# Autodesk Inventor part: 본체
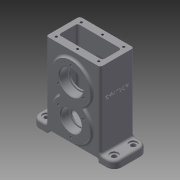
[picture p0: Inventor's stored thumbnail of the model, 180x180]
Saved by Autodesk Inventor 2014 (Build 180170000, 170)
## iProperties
Created: 2020-03
Part Number: 본체
Material: Aluminum 6061
Document SubType Name: Modeling
Designer: mduedu
Density: 2.71 g/cm^3
Appearance: Default
Mass: 597.031 g
Surface Area: 576.062 cm^2
Volume: 220.307 cm^3
Author: mduedu
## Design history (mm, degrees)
sketch "스케치1"
  geometry: L1 (-56, 0)-(56, 0); L2 (56, 0)-(56, 10); L3 (-56, 10)-(-56, 0); L4 (37, 10)-(37, 114); L5 (37, 114)-(-37, 114); L6 (-37, 114)-(-37, 10); L7 (56, 10)-(37, 10); L8 (-37, 10)-(-56, 10); L9 (0, 0)-(0, 114); 1 further point
  constraints: 18 end point, 5 parallel, 2 midpoint, 2 vertical, 1 coincident, 1 horizontal, 1 perpendicular
  dimensions: "d0" = 112 distance of L1.start L1.end; "d2" = 10 distance of L1.end L2.end; "d3" = 114 distance between parallel lines of L5 L1; "d4" = 74 distance between parallel lines of L4 L6
extrude "돌출1" new body sketch "스케치1" stored distance "d5" = 46; taper "d6" = 0 deg
sketch "스케치2"
  geometry: L1 (56, 0)-(-56, 0) reference; C1 r 26 at (0, 34); C2 r 26 at (0, 79); 1 further point
  constraints: 2 centre point, 2 vertical alignment, 1 equal radius
  dimensions: "d7" = 52 diameter of C2; "d9" = 34 distance from line of C1.centre L1; "d10" = 45 distance of C2.centre C1.centre
extrude "돌출2" join sketch "스케치2" stored distance "d11" = 52; taper "d12" = 0 deg
fillet "모깎기1" dims "d13" = 3
fillet "모깎기2" dims "d14" = 3
fillet "모깎기3" dims "d15" = 10
fillet "모깎기4" dims "d16" = 3
fillet "모깎기5" dims "d17" = 3
sketch "스케치3"
  geometry: L1 (-30, 114)-(30, 114); L2 (30, 114)-(30, 13); L3 (30, 13)-(-30, 13); L4 (-30, 13)-(-30, 114); L5 (-34, 114)-(34, 114) reference; L6 (46, 0)-(-46, 0) reference; 2 further points
  constraints: 8 end point, 2 parallel, 1 collinear, 1 horizontal, 1 midpoint, 1 perpendicular, 1 vertical alignment
  dimensions: "d18" = 60 distance between parallel lines of L2 L4; "d20" = 13 distance between parallel lines of L3 L6
extrude "돌출3" cut sketch "스케치3" stored distance "d21" = 26; taper "d22" = 0 deg
fillet "모깎기6" dims "d23" = 3
fillet "모깎기7" dims "d24" = 3
sketch "스케치4"
  geometry: L1 (-35, 0)-(35, 0); L2 (35, 0)-(35, 5); L3 (35, 5)-(-35, 5); L4 (-35, 5)-(-35, 0); 2 further points
  constraints: 8 end point, 2 parallel, 1 coincident, 1 horizontal, 1 midpoint, 1 perpendicular
  dimensions: "d25" = 70 distance of L1.start L1.end; "d27" = 5 distance of L1.end L2.end
extrude "돌출4" cut sketch "스케치4" stored distance "d28" = 26; taper "d29" = 0 deg
fillet "모깎기8" dims "d30" = 3
sketch "스케치5"
  geometry: A1 r 10 centre (-86, 33) between (-86, 43) and (-96, 33) reference; A2 r 10 centre (-86, 7) between (-96, 7) and (-86, -3) reference; A3 r 10 centre (6, 7) between (6, -3) and (16, 7) reference; A4 r 10 centre (6, 33) between (16, 33) and (6, 43) reference; 5 further points
  constraints: 4 coincident
hole "구멍1" sketch "스케치5" at (-86, 33), (-86, 7), (6, 7), (6, 33) diameter "d31" = 6.6; stored, may be unused: countersink angle "d35" = 90 deg, drill point angle "d37" = 118 deg; dims "d32" = 6, "d33" = 11, "d34" = 2, "d36" = 8
sketch "스케치6"
  geometry: A1 r 26 centre (0, 34) between (-16.403, 54.172) and (16.403, 54.172) reference; A2 r 3 centre (18.296, 56.5) between (16.403, 58.828) and (16.403, 54.172) reference; A3 r 26 centre (0, 79) between (16.403, 58.828) and (-16.403, 58.828) reference; A4 r 3 centre (-18.296, 56.5) between (-16.403, 54.172) and (-16.403, 58.828) reference; 2 further points
  constraints: 1 coincident
hole "구멍2" sketch "스케치6" at (0, 79) diameter "d38" = 28; stored, may be unused: countersink angle "d42" = 90 deg, drill point angle "d44" = 118 deg; dims "d39" = 6, "d40" = 32, "d41" = 11, "d43" = 8
sketch "스케치7"
  geometry: C1 r 16 at (0, 79) reference; A1 r 26 centre (0, 34) between (-16.403, 54.172) and (16.403, 54.172) reference; A2 r 3 centre (18.296, 56.5) between (16.403, 58.828) and (16.403, 54.172) reference; A3 r 26 centre (0, 79) between (16.403, 58.828) and (-16.403, 58.828) reference; A4 r 3 centre (-18.296, 56.5) between (-16.403, 54.172) and (-16.403, 58.828) reference; 2 further points
  constraints: 1 coincident
hole "구멍3" sketch "스케치7" at (0, 34) diameter "d45" = 24; stored, may be unused: countersink angle "d49" = 90 deg, drill point angle "d51" = 118 deg; dims "d46" = 6, "d47" = 28, "d48" = 11, "d50" = 8
sketch "스케치8"
  geometry: C1 r 14 at (0, 34) reference; A1 r 26 centre (0, 34) between (-16.403, 54.172) and (16.403, 54.172) reference; A2 r 3 centre (18.296, 56.5) between (16.403, 58.828) and (16.403, 54.172) reference; A3 r 26 centre (0, 79) between (16.403, 58.828) and (-16.403, 58.828) reference; A4 r 3 centre (-18.296, 56.5) between (-16.403, 54.172) and (-16.403, 58.828) reference; 2 further points
  constraints: 1 coincident
hole "구멍4" sketch "스케치8" at (0, 79) diameter "d52" = 24; stored, may be unused: countersink angle "d56" = 90 deg, drill point angle "d58" = 118 deg; dims "d53" = 6, "d54" = 28, "d55" = 11, "d57" = 8
sketch "스케치9" dims "d59" = 40
  geometry: C1 r 14 at (0, 34) reference; C2 r 16 at (0, 79) reference; A1 r 26 centre (0, 34) between (-16.403, 54.172) and (16.403, 54.172) reference; A2 r 3 centre (18.296, 56.5) between (16.403, 58.828) and (16.403, 54.172) reference; A3 r 26 centre (0, 79) between (16.403, 58.828) and (-16.403, 58.828) reference; A4 r 3 centre (-18.296, 56.5) between (-16.403, 54.172) and (-16.403, 58.828) reference; 3 further points
  constraints: 2 vertical alignment, 1 coincident, 2 other
hole "구멍5" sketch "스케치9" at (0, 99) diameter "d61" = 3.242; stored, may be unused: countersink angle "d65" = 90 deg, drill point angle "d67" = 118 deg; dims "d62" = 8, "d63" = 28, "d64" = 11, "d66" = 10
sketch "스케치10" dims "d71" = 40
  geometry: C1 r 1.621 at (17.321, 69) reference; C2 r 1.621 at (-17.321, 69) reference; C3 r 1.621 at (0, 99) reference; C4 r 14 at (0, 34) reference; C5 r 16 at (0, 79) reference; A1 r 26 centre (0, 34) between (-16.403, 54.172) and (16.403, 54.172) reference; A2 r 3 centre (18.296, 56.5) between (16.403, 58.828) and (16.403, 54.172) reference; A3 r 26 centre (0, 79) between (16.403, 58.828) and (-16.403, 58.828) reference; A4 r 3 centre (-18.296, 56.5) between (-16.403, 54.172) and (-16.403, 58.828) reference; 3 further points
  constraints: 2 vertical alignment, 1 coincident, 2 other
hole "구멍6" sketch "스케치10" at (0, 14) diameter "d72" = 3.242; stored, may be unused: countersink angle "d76" = 90 deg, drill point angle "d78" = 118 deg; dims "d73" = 8, "d74" = 28, "d75" = 11, "d77" = 10
sketch "스케치11"
  geometry: L1 (5, 6)-(63, 6); L2 (63, 6)-(63, 40); L3 (63, 40)-(5, 40); L4 (5, 40)-(5, 6); L5 (5, 6)-(63, 40); L6 (63, 6)-(5, 40); 7 further points
  constraints: 12 end point, 4 coincident, 4 midpoint, 2 parallel, 1 horizontal, 1 perpendicular
  dimensions: "d82" = 58 distance of L3.end L2.end; "d83" = 34 distance of L2.end L1.end
hole "구멍7" sketch "스케치11" at (5, 40), (63, 40), (63, 6), (5, 6), (34, 6), (34, 40) diameter "d84" = 3.242; stored, may be unused: countersink angle "d88" = 90 deg, drill point angle "d90" = 118 deg; dims "d85" = 8, "d86" = 28, "d87" = 11, "d89" = 10
fillet "모깎기9" dims "d91" = 0.3
chamfer "모따기1" distance "d92" = 1; stored, may be unused: second distance "d93" = 2, angle "d94" = 45 deg
sketch "스케치12"
  geometry: 2 further points
  constraints: 1 coincident
hole "구멍8" sketch "스케치12" at (0, -23) diameter "d95" = 4.917; stored, may be unused: countersink angle "d99" = 90 deg, drill point angle "d101" = 118 deg; dims "d96" = 8, "d97" = 12, "d98" = 1, "d100" = 10
sketch "스케치13"
  geometry: L1 (33, -13)-(7, -13) reference; L2 (40, 101)-(0, 101) reference; 3 further points
  constraints: 1 midpoint, 1 vertical alignment, 1 other
  dimensions: "d102" = 40 distance from line of point (20, 61) L2
feature "엠보싱1" sketch "스케치13" dims "d0" = 112, "d2" = 10, "d3" = 114, "d4" = 74, "d13" = 3, "d103" = 0.5, "d104" = 0
node "솔리드1"
mirror "대칭1"
pattern_circular "원형 패턴1" dims angle "d69" = 360 deg
pattern_circular "원형 패턴2" dims angle "d80" = 360 deg
mirror "대칭2"
node "투영된 루프1"
node "투영된 루프2"
node "투영된 루프3"
node "투영된 루프4"
node "투영된 루프5"
